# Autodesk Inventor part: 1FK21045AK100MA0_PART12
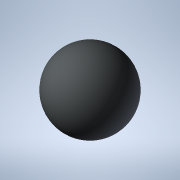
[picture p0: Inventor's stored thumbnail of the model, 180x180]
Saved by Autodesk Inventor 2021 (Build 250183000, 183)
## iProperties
Created: 2025-04
Part Number: 1FK21045AK100MA0_PART12
Material: Generic
Catalog Web Link: www.3dfindit.com
Description: -Servo synchronous motor
Document SubType Name: Modeling
Designer: psAdmin
Mass: 0.137258 g
Surface Area: 1.2868 cm^2
Volume: 0.137258 cm^3
Density: 1 g/cm^3
Appearance: PSOLRGB-212-217-219
Category: PARTsolutions
Title: 1FK21045AK100MA0_PART12
Author: Cadenas PARTsolutions
Comments: Servo synchronous motor
Sending System: PARTsolutions
Preprocessor: ST-DEVELOPER v19.3
PSOL_IDENT_0: {$CADENAS_DATA/23d-libs/siemens_ag/_cat_/e0/5f/1fk21045ak100ma0.prj},216 {VTYP=3D},{NB=1FK21045AK100
PSOL_IDENT_1: MA0_PART12},{LINA=1FK21045AK100MA0_PART12},{NN=1FK21045AK100MA0_PART12},{NOPRJ=TRUE},{DATE=19.08.202
PSOL_IDENT_2: 5 14:01:03},{GEOMDATE=30.07.2025 02:01:57},{VERSION=},{LINEID=10},{WBVAR=},{WBNUMERIC=}  {NB=1FK2104
PSOL_IDENT_3: 5AK100MA0_PART12},{LINA=1FK21045AK100MA0_PART12},{KT=DUMMY},{PREVIEW=../../../_pool_/0f/2c/p_d211_xx
PSOL_IDENT_4: _00438j.png},{DESCSHORT=SIMOTICS S-1FK2 HD, SINAMICS S210 3AC 400V-480V, 1.7 Nm, 6000 rpm},{DESCLONG=
PSOL_IDENT_5: SIMOTICS S-1FK2 HD servo motor M0=2.4 Nm; PN = 1.07 kW at nN=6000 rpm (380-480 V); PN = 0.75 kW at n
PSOL_IDENT_6: N=3000 rpm (200-240 V); with holding brake; degree of protection IP64; cylindrical shaft D19x40mm; a
PSOL_IDENT_7: bsolute encoder 22-bit + 12-bit multiturn (encoder AM22DQC); with OCC interface; plug size M17, rota
PSOL_IDENT_8: table; SIMOTICS S-1FK2 servomotorfor a wide range of uses in industrial environments. SIMOTICS S‑1FK
PSOL_IDENT_9: 2 servomotors are compact synchronous motors with a high dynamic performance that set themselves apa
PSOL_IDENT_10: rt as a result of their high power density, degree of protection and overload capability. The motors
PSOL_IDENT_11: are available in two variants: as High Dynamic variant (highest dynamic performance as a result of
PSOL_IDENT_12: the low intrinsic moment of inertia for applications demanding a high dynamic performance with low m
PSOL_IDENT_13: oved masses) - and as Compact variant (precise and stable closed-loop control for medium up to large
PSOL_IDENT_14: moved masses as a result of a medium intrinsic moment of inertia). SIMOTICSS‑1FK2 servomotors fully
PSOL_IDENT_15: exploit their strengths in a system with the SINAMICSS210 frequency converter and simple connection
PSOL_IDENT_16: using the one cable connection (OCC). Advantages include the short control and positioning times, f
PSOL_IDENT_17: ast and precise correction of disturbing quantities as well as stable control with a high dynamic pe
PSOL_IDENT_18: rformance. The servo motors can be configured to address a wide range of requirements. For example w
PSOL_IDENT_19: ith and without holding brake, IP64 or IP65 degree of protection, singleturn or multiturn absolute e
PSOL_IDENT_20: ncoders - to name just a few. Further, the servomotors are available in different shaft heights exte
PSOL_IDENT_21: nding from 20 to 100. A shaft sealing ring is available to achieve an IP65 degree of protection and
PSOL_IDENT_22: for subsequent mounting at the motor or as spare part. SIMOTICS - the optimum motor for each and eve
PSOL_IDENT_23: ry motion control application.},{INTNO=804766807114},{SUPPLIERALTNO=1FK2104-5AK10-0MA0},{MANUID=1FK2
PSOL_IDENT_24: 1045AK100MA0},{MANUNAME=Siemens},{MANUTYPEDESC=Synchronous motor 1FK2-HD 2,39 Nm},{AAU732=SIMOTICS},
PSOL_IDENT_25: {AAO057=S-1FK2},{AAU734=SIMOTICS S-1FK2 HD servo motor M0=2.4 Nm; PN = 1.07 kW at nN=6000 rpm (380-4
PSOL_IDENT_26: 80 V); PN = 0.75 kW at nN=3000 rpm (200-240 V); with holding brake; degree of protection IP64; cylin
PSOL_IDENT_27: drical shaft D19x40mm; absolute encoder 22-bit + 12-bit multiturn (encoder AM22DQC); with OCC interf
PSOL_IDENT_28: ace; plug size M17, rotatable;},{AAW338=Synchronous motor 1FK2-HD 2,39 Nm},{AAO742=SIMOTICS},{AAO663=
PSOL_IDENT_29: 4042948691236},{NOCUPEROU=1},{PRICEQUANTITY=1},{QUANTITYMIN=1},{QUANTITYINT=1},{CTN=85015100},{COO=D
PSOL_IDENT_30: E},{AAO676=1FK2104-5AK10-0MA0},{AAO677=Siemens AG},{ORDERUNIT=C62},{CONTENTUNIT=C62}
NB: 1FK21045AK100MA0_PART12
NT: Servo synchronous motor
NBSYN: $MANUID._PART12
LINA: 1FK21045AK100MA0_PART12
CATALOG: SIEMENS
PREVIEW: ../../../_pool_/0f/2c/p_d211_xx_00438j.png
DESCSHORT: SIMOTICS S-1FK2 HD, SINAMICS S210 3AC 400V-480V, 1.7 Nm, 6000 rpm
DESCLONG: SIMOTICS S-1FK2 HD servo motor M0=2.4 Nm; PN = 1.07 kW at nN=6000 rpm (380-480 V); PN = 0.75 kW at nN=3000 rpm (200-240 V); with holding brake; degree of protec
INTNO: 804766807114
SUPPLIERALTNO: 1FK2104-5AK10-0MA0
MANUID: 1FK21045AK100MA0
MANUNAME: Siemens
MANUTYPEDESC: Synchronous motor 1FK2-HD 2,39 Nm
AAU732: SIMOTICS
AAO057: S-1FK2
AAU734: SIMOTICS S-1FK2 HD servo motor M0=2.4 Nm; PN = 1.07 kW at nN=6000 rpm (380-480 V); PN = 0.75 kW at nN=3000 rpm (200-240 V); with holding brake; degree of protec
AAW338: Synchronous motor 1FK2-HD 2,39 Nm
AAO742: SIMOTICS
AAO663: 4042948691236.0
NOCUPEROU: 1
PRICEQUANTITY: 1
QUANTITYMIN: 1
QUANTITYINT: 1
CTN: 85015100
COO: DE
ARTICLENO: 1FK21045AK100MA0_PART12
BOMINFO: 1FK21045AK100MA0_PART12
CREATOR: CADENAS GmbH
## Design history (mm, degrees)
feature "2025_04_17_15_45_15_0090"
body "Solid1"
